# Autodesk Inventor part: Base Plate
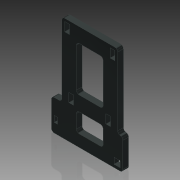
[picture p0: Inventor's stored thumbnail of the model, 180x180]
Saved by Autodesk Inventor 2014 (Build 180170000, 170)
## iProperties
Created: 2015-07
Part Number: Base Plate
Material: Generic
Document SubType Name: Modeling
Designer: Brad Factor
Density: 1 g/cm^3
Appearance: Gunmetal - Polished
Author: Brad Factor
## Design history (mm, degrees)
sketch "Sketch1"
  geometry: L1 (-23.216, 66.636)-(-27.978, 66.636); L2 (-27.978, 66.636)-(-27.978, 76.161); L3 (-27.978, 76.161)-(-23.216, 76.161); L4 (-23.216, 76.161)-(-23.216, 66.636); L5 (23.216, 76.161)-(27.978, 76.161); L6 (27.978, 76.161)-(27.978, 66.636); L7 (27.978, 66.636)-(23.216, 66.636); L8 (23.216, 66.636)-(23.216, 76.161); L9 (-23.216, 9.525)-(-18.453, 9.525); L10 (-18.453, 9.525)-(-18.453, 0); L11 (-18.453, 0)-(-23.216, 0); L12 (-23.216, 0)-(-23.216, 9.525); L13 (18.453, 9.525)-(23.216, 9.525); L14 (23.216, 9.525)-(23.216, 0); L15 (23.216, 0)-(18.453, 0); L16 (18.453, 0)-(18.453, 9.525); L17 (-39.745, -21.13)-(-36.57, -21.13); L18 (-36.57, -21.13)-(-36.57, -27.48); L19 (-36.57, -27.48)-(-39.745, -27.48); L20 (-39.745, -27.48)-(-39.745, -21.13); L21 (27.508, -28.331)-(33.858, -28.331); L22 (33.858, -28.331)-(33.858, -34.681); L23 (33.858, -34.681)-(27.508, -34.681); L24 (27.508, -34.681)-(27.508, -28.331); L25 (-18.453, 4.763)-(18.453, 4.763); L26 (-22.962, 76.415)-(-28.232, 76.415); L27 (-28.232, 76.415)-(-28.232, 66.382); L28 (-28.232, 66.382)-(-22.962, 66.382); L29 (-22.962, 66.382)-(-22.962, 76.415); L30 (28.232, 76.415)-(22.962, 76.415); L31 (22.962, 76.415)-(22.962, 66.382); L32 (22.962, 66.382)-(28.232, 66.382); L33 (28.232, 66.382)-(28.232, 76.415); L34 (-18.199, 9.779)-(-23.47, 9.779); L35 (-23.47, 9.779)-(-23.47, -0.254); L36 (-23.47, -0.254)-(-18.199, -0.254); L37 (-18.199, -0.254)-(-18.199, 9.779); L38 (18.199, -0.254)-(23.47, -0.254); L39 (23.47, -0.254)-(23.47, 9.779); L40 (23.47, 9.779)-(18.199, 9.779); L41 (18.199, 9.779)-(18.199, -0.254); L42 (34.112, -28.077)-(27.254, -28.077); L43 (27.254, -28.077)-(27.254, -34.935); L44 (27.254, -34.935)-(34.112, -34.935); L45 (34.112, -34.935)-(34.112, -28.077); L46 (-36.316, -20.876)-(-39.999, -20.876); L47 (-39.999, -20.876)-(-39.999, -27.734); L48 (-39.999, -27.734)-(-36.316, -27.734); L49 (-36.316, -27.734)-(-36.316, -20.876); L50 (31.407, 79.59)-(19.787, 79.59); L51 (19.787, 79.59)-(19.787, 63.207); L52 (19.787, 63.207)-(31.407, 63.207); L53 (31.407, 63.207)-(31.407, 79.59); L54 (-19.787, 79.59)-(-31.407, 79.59); L55 (-31.407, 79.59)-(-31.407, 63.207); L56 (-31.407, 63.207)-(-19.787, 63.207); L57 (-19.787, 63.207)-(-19.787, 79.59); L58 (-15.024, 12.954)-(-26.645, 12.954); L59 (-26.645, 12.954)-(-26.645, -3.429); L60 (-26.645, -3.429)-(-15.024, -3.429); L61 (-15.024, -3.429)-(-15.024, 12.954); L62 (26.645, 12.954)-(26.645, -3.429); L63 (26.645, -3.429)-(15.024, -3.429); L64 (15.024, -3.429)-(15.024, 12.954)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; 3 further points
  constraints: 180 end point, 40 parallel, 20 perpendicular, 13 horizontal, 9 collinear, 6 equal length, 6 midpoint, 3 vertical, 2 vertical alignment, 1 horizontal alignment, 1 point on line, 36 other
  dimensions: "d0" = 9.525 distance of L1.end L2.end; "d1" = 4.7625 distance of L2.end L3.end; "d2" = 46.4312 distance between parallel lines of L8 L4; "d3" = 36.9062 distance between parallel lines of L16 L10; "d4" = 57.11139 distance between parallel lines of L13 L7; "d5" = 6.35 distance of L21.end L22.end; "d6" = 6.35 distance of L21.start L21.end; "d7" = 6.35 distance of L19.end L17.start; "d8" = 3.175 distance of L17.start L17.end; "d9" = 13.35405 distance between parallel lines of L12 L18; "d10" = 21.13026 distance between parallel lines of L17 L11; "d11" = 28.33116 distance between parallel lines of L21 L15; "d12" = 4.2926 distance between parallel lines of L24 L14; "d13" = 0.254 distance between parallel lines of L4 L29; "d14" = 0.254 distance between parallel lines of L8 L31; "d15" = 0.254 distance between parallel lines of L9 L34; "d16" = 0.254 distance between parallel lines of L38 L15; "d17" = 0.254 distance between parallel lines of L48 L19; "d18" = 0.254 distance between parallel lines of L23 L44; "d20" = 3.175 distance between parallel lines of L28 L56; "d21" = 3.175 distance between parallel lines of L34 L58; "d22" = 3.175 distance between parallel lines of L40 L65; "d23" = 3.175 distance between parallel lines of L44 L68; "d24" = 3.175 distance between parallel lines of L48 L72; "d25" = 3.175 distance between parallel lines of L50 L30
extrude "Plate" new body sketch "Sketch1" distance "d26" = 6.35; taper "d27" = 0 deg
fillet "1/8\" Fillets" dims "d28" = 3.175
chamfer "30 mil Installation Chamfers" distance "d32" = 0.762; stored, may be unused: second distance "d33" = 3.175, angle "d34" = 45 deg
body "Solid1"
